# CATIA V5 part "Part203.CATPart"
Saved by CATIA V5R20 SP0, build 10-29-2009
Part number: FA 168700-1
Revision: ANY
Definition: UNKNOWN
Nomenclature: FA 168700-1
Source: Unknown
Bounding box of the stored display mesh (mm): x -3.804 to 3.804, y 0.28 to 2.5, z -4 to 4
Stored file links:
  C:\Users\Utente\Desktop\IO LAVORO\3D X SITO CF\CUMSA\3D files FA\FA 168712-20\Part203.CATPart

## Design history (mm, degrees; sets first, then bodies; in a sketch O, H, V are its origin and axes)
Body1 "Cortar-Extruir1" (main body)
  Solid1: solid without history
